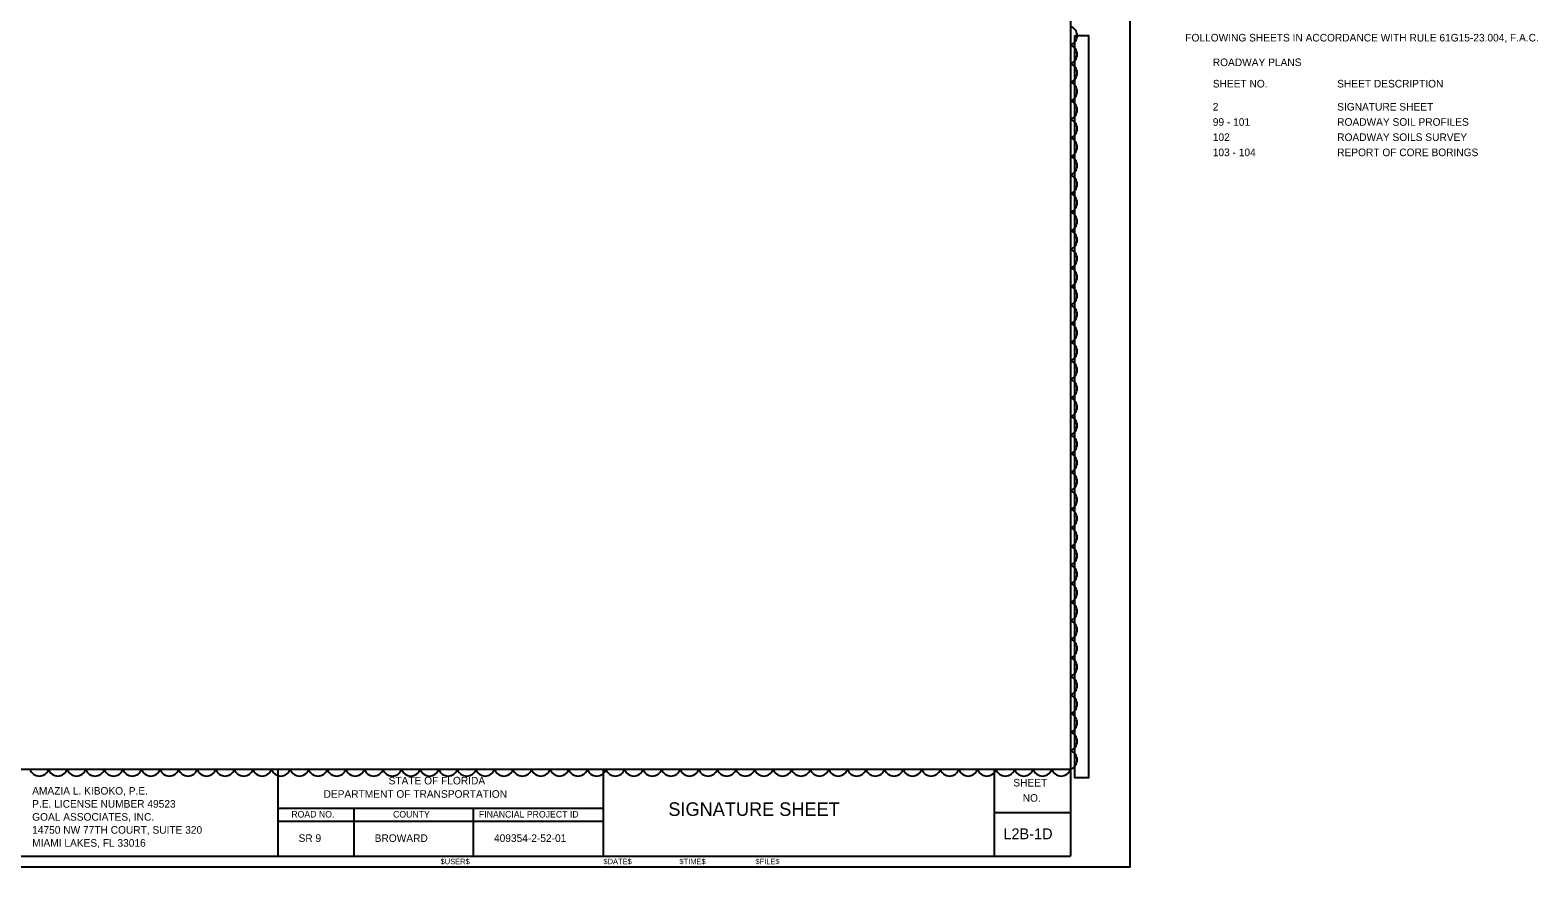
# Model space of a CAD drawing. Extents: x -816.9 to -790.1, y -2199.5 to -2184.5.
# Drawn here: x -804.97 to -791.08, y -2199.5 to -2191.79 of the extents above; entities that cross this region are included whole.
import ezdxf

# ---------------------------------------------------------------- set-up
doc = ezdxf.new("R2010")
doc.units = 0
for name, color, linetype in [('Cloud_dp', 7, 'Continuous'), ('PlotBorder_dp', 7, 'Continuous'), ('ScratchEle_dp', 7, 'Continuous'), ('SheetBorder_dp', 7, 'Continuous'), ('SheetLines_dp', 7, 'Continuous'), ('TextMinor', 7, 'Continuous'), ('TextMisc', 7, 'Continuous'), ('TextNotes', 7, 'Continuous'), ('TextShtNo', 7, 'Continuous'), ('TextTitle', 7, 'Continuous')]:
    doc.layers.add(name, color=color, linetype=linetype)

msp = doc.modelspace()

# ---------------------------------------------------------------- linework, layer by layer
at = {"layer": 'Cloud_dp'}
for centre, start, end in [((-795.413, -2191.841), 287.5, 72.5), ((-795.413, -2192.012), 287.5, 72.5), ((-795.413, -2192.184), 287.5, 72.5), ((-795.413, -2192.355), 287.5, 72.5), ((-795.413, -2192.526), 287.5, 72.5), ((-795.413, -2192.697), 287.5, 72.5), ((-795.413, -2192.868), 287.5, 72.5), ((-795.413, -2193.039), 287.5, 72.5), ((-795.413, -2193.21), 287.5, 72.5), ((-795.413, -2193.381), 287.5, 72.5), ((-795.413, -2193.553), 287.5, 72.5), ((-795.413, -2193.724), 287.5, 72.5), ((-795.413, -2193.895), 287.5, 72.5), ((-795.413, -2194.066), 287.5, 72.5), ((-795.413, -2194.237), 287.5, 72.5), ((-795.413, -2194.408), 287.5, 72.5), ((-795.413, -2194.579), 287.5, 72.5), ((-795.413, -2194.75), 287.5, 72.5), ((-795.413, -2194.922), 287.5, 72.5), ((-795.413, -2195.093), 287.5, 72.5), ((-795.413, -2195.264), 287.5, 72.5), ((-795.413, -2195.435), 287.5, 72.5), ((-795.413, -2195.606), 287.5, 72.5), ((-795.413, -2195.777), 287.5, 72.5), ((-795.413, -2195.948), 287.5, 72.5), ((-795.413, -2196.119), 287.5, 72.5), ((-795.413, -2196.29), 287.5, 72.5), ((-795.413, -2196.462), 287.5, 72.5), ((-795.413, -2196.633), 287.5, 72.5), ((-795.413, -2196.804), 287.5, 72.5), ((-795.413, -2196.975), 287.5, 72.5), ((-795.413, -2197.146), 287.5, 72.5), ((-795.413, -2197.317), 287.5, 72.5), ((-795.413, -2197.488), 287.5, 72.5), ((-795.413, -2197.659), 287.5, 72.5), ((-795.413, -2197.831), 287.5, 72.5), ((-795.413, -2198.002), 287.5, 72.5), ((-795.413, -2198.173), 287.5, 72.5), ((-795.413, -2198.344), 287.5, 72.5), ((-795.413, -2198.515), 287.5, 72.5), ((-804.883, -2198.574), 197.5, 342.5), ((-804.712, -2198.574), 197.5, 342.5), ((-804.541, -2198.574), 197.5, 342.5), ((-804.37, -2198.574), 197.5, 342.5), ((-804.199, -2198.574), 197.5, 342.5), ((-804.027, -2198.574), 197.5, 342.5), ((-803.856, -2198.574), 197.5, 342.5), ((-803.685, -2198.574), 197.5, 342.5), ((-803.514, -2198.574), 197.5, 342.5), ((-803.343, -2198.574), 197.5, 342.5), ((-803.172, -2198.574), 197.5, 342.5), ((-803.001, -2198.574), 197.5, 342.5), ((-802.83, -2198.574), 197.5, 342.5), ((-802.658, -2198.574), 197.5, 342.5), ((-802.487, -2198.574), 197.5, 342.5), ((-802.316, -2198.574), 197.5, 342.5), ((-802.145, -2198.574), 197.5, 342.5), ((-801.974, -2198.574), 197.5, 342.5), ((-801.803, -2198.574), 197.5, 342.5), ((-801.632, -2198.574), 197.5, 342.5), ((-801.461, -2198.574), 197.5, 342.5), ((-801.289, -2198.574), 197.5, 342.5), ((-801.118, -2198.574), 197.5, 342.5), ((-800.947, -2198.574), 197.5, 342.5), ((-800.776, -2198.574), 197.5, 342.5), ((-800.605, -2198.574), 197.5, 342.5), ((-800.434, -2198.574), 197.5, 342.5), ((-800.263, -2198.574), 197.5, 342.5), ((-800.092, -2198.574), 197.5, 342.5), ((-799.921, -2198.574), 197.5, 342.5), ((-799.749, -2198.574), 197.5, 342.5), ((-799.578, -2198.574), 197.5, 342.5), ((-799.407, -2198.574), 197.5, 342.5), ((-799.236, -2198.574), 197.5, 342.5), ((-799.065, -2198.574), 197.5, 342.5), ((-798.894, -2198.574), 197.5, 342.5), ((-798.723, -2198.574), 197.5, 342.5), ((-798.552, -2198.574), 197.5, 342.5), ((-798.38, -2198.574), 197.5, 342.5), ((-798.209, -2198.574), 197.5, 342.5), ((-798.038, -2198.574), 197.5, 342.5), ((-797.867, -2198.574), 197.5, 342.5), ((-797.696, -2198.574), 197.5, 342.5), ((-797.525, -2198.574), 197.5, 342.5), ((-797.354, -2198.574), 197.5, 342.5), ((-797.183, -2198.574), 197.5, 342.5), ((-797.011, -2198.574), 197.5, 342.5), ((-796.84, -2198.574), 197.5, 342.5), ((-796.669, -2198.574), 197.5, 342.5), ((-796.498, -2198.574), 197.5, 342.5), ((-796.327, -2198.574), 197.5, 342.5), ((-796.156, -2198.574), 197.5, 342.5), ((-795.985, -2198.574), 197.5, 342.5), ((-795.814, -2198.574), 197.5, 342.5), ((-795.642, -2198.574), 197.5, 342.5), ((-795.471, -2198.574), 197.5, 342.5)]:
    msp.add_arc(centre, 0.0897, start, end, dxfattribs=at)
at = {"layer": 'PlotBorder_dp'}
msp.add_lwpolyline([(-811.336, -2199.501), (-794.836, -2199.501), (-794.836, -2188.901), (-811.336, -2188.901)], close=True, dxfattribs=at)
at = {"layer": 'ScratchEle_dp'}
msp.add_lwpolyline([(-795.346, -2191.838), (-795.218, -2191.838), (-795.218, -2198.68), (-795.346, -2198.68)], close=True, dxfattribs=at)
at = {"layer": 'SheetBorder_dp'}
for p, q in [((-795.386, -2189.001), (-795.386, -2199.401)), ((-810.786, -2198.601), (-795.386, -2198.601)), ((-810.786, -2199.401), (-795.386, -2199.401))]:
    msp.add_line(p, q, dxfattribs=at)
at = {"layer": 'SheetLines_dp'}
for p, q in [((-802.686, -2198.601), (-802.686, -2199.401)), ((-799.686, -2199.401), (-799.686, -2198.601)), ((-796.086, -2199.401), (-796.086, -2198.601)), ((-802.686, -2198.961), (-799.686, -2198.961)), ((-801.986, -2198.961), (-801.986, -2199.401)), ((-800.886, -2198.961), (-800.886, -2199.401)), ((-802.686, -2199.081), (-799.686, -2199.081)), ((-796.086, -2199.001), (-795.386, -2199.001))]:
    msp.add_line(p, q, dxfattribs=at)

# ---------------------------------------------------------------- texts
at = {"layer": 'TextMinor'}
msp.add_text('$USER$', height=0.05, dxfattribs=at).set_placement((-801.187, -2199.476))
for s, p in [('$DATE$', (-799.687, -2199.476)), ('$TIME$', (-798.987, -2199.476)), ('$FILE$', (-798.287, -2199.476))]:
    msp.add_text(s, height=0.05, rotation=360, dxfattribs=at).set_placement(p)
at = {"layer": 'TextMisc'}
for s, height, p in [('FOLLOWING SHEETS IN ACCORDANCE WITH RULE 61G15-23.004, F.A.C.', 0.07, (-794.327, -2191.894)), ('ROADWAY PLANS', 0.07, (-794.074, -2192.121)), ('STATE OF FLORIDA', 0.07, (-801.666, -2198.741)), ('DEPARTMENT OF TRANSPORTATION', 0.07, (-802.265, -2198.864)), ('ROAD NO.', 0.06, (-802.562, -2199.046)), ('COUNTY', 0.06, (-801.625, -2199.046)), ('FINANCIAL PROJECT ID', 0.06, (-800.834, -2199.046)), ('       SIGNATURE SHEET         ', 0.125, (-799.414, -2199.031)), (' SR 9  ', 0.07, (-802.521, -2199.271)), ('  BROWARD   ', 0.07, (-801.846, -2199.271)), ('409354-2-52-01', 0.07, (-800.695, -2199.271))]:
    msp.add_text(s, height=height, dxfattribs=at).set_placement(p)
for s, p in [('SHEET', (-795.911, -2198.76)), ('NO.', (-795.825, -2198.9))]:
    msp.add_text(s, height=0.07, rotation=359.8607, dxfattribs=at).set_placement(p)
at = {"layer": 'TextNotes'}
for s, p in [('SHEET NO.', (-794.074, -2192.318)), ('SHEET DESCRIPTION', (-792.928, -2192.318)), ('2', (-794.074, -2192.531)), ('SIGNATURE SHEET', (-792.928, -2192.531)), ('99 - 101', (-794.074, -2192.671)), ('ROADWAY SOIL PROFILES', (-792.928, -2192.671)), ('102', (-794.074, -2192.811)), ('ROADWAY SOILS SURVEY', (-792.928, -2192.811)), ('103 - 104', (-794.074, -2192.951)), ('REPORT OF CORE BORINGS', (-792.928, -2192.951))]:
    msp.add_text(s, height=0.07, dxfattribs=at).set_placement(p)
at = {"layer": 'TextShtNo'}
msp.add_text('L2B-1D', height=0.1, dxfattribs=at).set_placement((-796.003, -2199.246))
at = {"layer": 'TextTitle'}
for s, p in [('AMAZIA L. KIBOKO, P.E.', (-804.949, -2198.835)), ('P.E. LICENSE NUMBER 49523', (-804.949, -2198.955)), ('GOAL ASSOCIATES, INC.', (-804.949, -2199.075)), ('14750 NW 77TH COURT, SUITE 320', (-804.949, -2199.195)), ('MIAMI LAKES, FL 33016', (-804.949, -2199.315))]:
    msp.add_text(s, height=0.07, dxfattribs=at).set_placement(p)

doc.saveas('drawing.dxf')
